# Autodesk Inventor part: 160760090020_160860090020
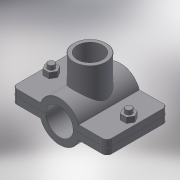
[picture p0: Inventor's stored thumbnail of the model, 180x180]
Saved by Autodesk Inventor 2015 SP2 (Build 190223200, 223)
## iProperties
Created: 2017-05
Part Number: 160760090020_160860090020
Material: Generic
Description: PLASSON SADDLE 90-2"
Document SubType Name: Modeling
Designer: KIM
Density: 1 g/cm^3
Appearance: Default
Author: KIM
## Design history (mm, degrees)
derived "16076.ipt"
feature "Solid1::16076.ipt"
feature "Solid2::16076.ipt"
tag "TaggingFeature1"
body "Solid1"
other parameters: "d0" = 99, "d1" = 141, "d2" = 45, "d4" = 105, "d5" = 0, "d6" = 7.05, "d7" = 141, "d8" = 0.1, "d10" = 0, "d11" = 0.9, "d14" = 73.6528, "d20" = 0.9, "d23" = 0.9, "d36" = 13, "d37" = 10.4, "d38" = 53, "d39" = 0, "d40" = 3, "d41" = 5, "d42" = 0, "d43" = 8, "d44" = 3, "d45" = 0, "d46" = 0.9, "d51" = 86, "d52" = 56.656, "d54" = 0, "d57" = 0, "d58" = 97.2, "d60" = 0, "d62" = 13, "d63" = 10.4, "d66" = 84.2, "G_" = 56.656, "A_" = 86, "L_" = 141, "L_1" = 105
